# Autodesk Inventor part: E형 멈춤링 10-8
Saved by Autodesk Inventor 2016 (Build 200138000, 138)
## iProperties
Created: 2024-08
Part Number: E형 멈춤링 10-8
Material: 일반
Description: 일반용 테이퍼 및 줄어든 횡단면 리테이닝 링 - E-링 외부 시리즈 3CM1 리테이닝 링
Document SubType Name: Modeling
Designer: pc-2
Density: 1 g/cm^3
Appearance: 기본값
Author: jhkim
Sending System: Autodesk Inventor 2025
Preprocessor: ST-DEVELOPER v20
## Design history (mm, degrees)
node "E형 멈춤링 10-81"
node "솔리드1"
body "Solid1"
